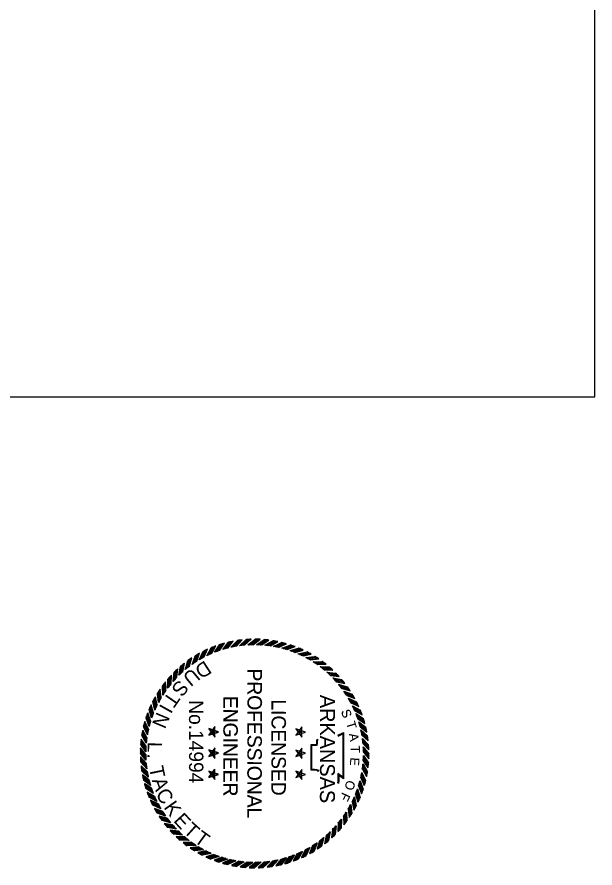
# Model space of a CAD drawing. Extents: x -206535075 to -206533174, y 123969740 to 123973355.
# Drawn here: x -206534124 to -206533511, y 123969740 to 123970644 of the extents above; entities that cross this region are included whole.
import ezdxf

# ---------------------------------------------------------------- set-up
doc = ezdxf.new("R2010")
doc.units = 0
doc.layers.add('54', color=7, linetype='Continuous')
doc.layers.add('Default', color=7, linetype='Continuous')

# ---------------------------------------------------------------- blocks, each defined once
blk = doc.blocks.new('STAR')
at = {"layer": 'Default'}
for p, q in [((0.0587, 0.0188), (-0.059, 0.0189)), ((-0.0589, 0.0188), (0.0363, -0.0505)), ((-0.0001, 0.0615), (-0.0366, -0.0504)), ((-0.0365, -0.0503), (0.0589, 0.0188)), ((-0.0085, 0), (0.009, 0)), ((0.0362, -0.0503), (0, 0.0617)), ((0, 0.0063), (0, -0.0085))]:
    blk.add_line(p, q, dxfattribs=at)
blk = doc.blocks.new('RP')
at = {"layer": 'Default'}
for p, q in [((-0.0781, 1.2656), (0.003, 1.33)), ((-0.058, 1.2667), (0.0216, 1.3299)), ((-0.0375, 1.2674), (0.0405, 1.3294)), ((-0.0176, 1.2679), (0.059, 1.3287))]:
    blk.add_line(p, q, dxfattribs=at)
for radius, start, end in [(1.33, 87.45624, 89.86992), (1.268, 90.79335, 93.53072)]:
    blk.add_arc((0, 0), radius, start, end, dxfattribs=at)

msp = doc.modelspace()

# ---------------------------------------------------------------- linework, layer by layer
at = {"layer": '54'}
msp.add_lwpolyline([(-206535027.79, 123970240.59), (-206533510.85, 123970240.59), (-206533510.85, 123973354.72), (-206535027.79, 123973354.72)], close=True, dxfattribs=at)
at = {"layer": 'Default'}
for points in [[(-206533804.55, 123969842.92), (-206533805.23, 123969843.76), (-206533806.25, 123969844.04), (-206533808.79, 123969844.33), (-206533812.18, 123969844.34), (-206533812.08, 123969871.71), (-206533807.51, 123969871.7), (-206533806.49, 123969871.69), (-206533806.15, 123969872.8), (-206533806.13, 123969876.7), (-206533805.08, 123969877.39)], [(-206533804.45, 123969842.94), (-206533805.13, 123969843.78), (-206533806.15, 123969844.06), (-206533808.69, 123969844.34), (-206533812.08, 123969844.34), (-206533812.08, 123969871.71), (-206533807.51, 123969871.71), (-206533806.49, 123969871.71), (-206533806.15, 123969872.82), (-206533806.15, 123969876.72), (-206533805.1, 123969877.41)], [(-206533803.95, 123969843.41), (-206533804.78, 123969844.44), (-206533806.1, 123969844.8), (-206533808.74, 123969845.1), (-206533811.4, 123969845.11), (-206533811.31, 123969870.93), (-206533807.51, 123969870.92), (-206533805.92, 123969870.91), (-206533805.37, 123969872.68), (-206533805.36, 123969876.27), (-206533804.65, 123969876.73)], [(-206533803.85, 123969843.44), (-206533804.69, 123969844.46), (-206533806.01, 123969844.82), (-206533808.65, 123969845.11), (-206533811.31, 123969845.11), (-206533811.31, 123969870.94), (-206533807.51, 123969870.94), (-206533805.92, 123969870.94), (-206533805.37, 123969872.71), (-206533805.37, 123969876.3), (-206533804.67, 123969876.76)], [(-206533783.55, 123969880.62), (-206533778.5, 123969882.93), (-206533778.63, 123969836.71), (-206533783.79, 123969840.85), (-206533783.74, 123969835.88), (-206533783.71, 123969833.14), (-206533784.02, 123969830.41)], [(-206533783.9, 123969881.42), (-206533777.76, 123969884.26), (-206533777.74, 123969835.22), (-206533782.88, 123969839.31), (-206533782.84, 123969835.98), (-206533782.8, 123969833.2), (-206533783.11, 123969830.42)], [(-206533783.58, 123969880.72), (-206533778.54, 123969883.04), (-206533778.51, 123969836.83), (-206533783.68, 123969840.94), (-206533783.62, 123969835.97), (-206533783.58, 123969833.24), (-206533783.88, 123969830.5)], [(-206533783.87, 123969881.33), (-206533777.72, 123969884.14), (-206533777.86, 123969835.1), (-206533782.99, 123969839.21), (-206533782.96, 123969835.88), (-206533782.94, 123969833.1), (-206533783.25, 123969830.32)]]:
    msp.add_lwpolyline(points, dxfattribs=at)

# ---------------------------------------------------------------- block references
for name, p, xscale, yscale, rotation in [('RP', (-206533872.18, 123969862.15), 91.17655343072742, 91.1765534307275, 22.30419999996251), ('RP', (-206533872.15, 123969861.95), 91.17655343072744, 91.17655343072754, 18.000000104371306), ('RP', (-206533872.18, 123969862.15), 91.17655343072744, 91.17655343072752, 17.804199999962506), ('RP', (-206533872.15, 123969861.95), 91.17655343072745, 91.17655343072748, 13.500000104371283), ('RP', (-206533872.18, 123969862.15), 91.17655343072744, 91.17655343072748, 13.304199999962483), ('RP', (-206533872.15, 123969861.95), 91.17655343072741, 91.17655343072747, 9.000000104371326), ('RP', (-206533872.18, 123969862.15), 91.17655343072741, 91.17655343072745, 8.804199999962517), ('RP', (-206533872.15, 123969861.95), 91.17655343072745, 91.17655343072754, 4.500000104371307), ('RP', (-206533872.18, 123969862.15), 91.17655343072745, 91.17655343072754, 4.3041999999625), ('RP', (-206533872.15, 123969861.95), 91.17655343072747, 91.17655343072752, 1.0437130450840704e-07), ('RP', (-206533872.18, 123969862.15), 91.17655343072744, 91.17655343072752, -0.1958000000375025), ('RP', (-206533872.15, 123969861.95), 91.17655343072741, 91.17655343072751, -4.499999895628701), ('RP', (-206533872.18, 123969862.15), 91.17655343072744, 91.1765534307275, -4.695800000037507), ('RP', (-206533872.15, 123969861.95), 91.17655343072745, 91.17655343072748, -8.999999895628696), ('RP', (-206533872.18, 123969862.15), 91.17655343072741, 91.17655343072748, -9.195800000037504), ('RP', (-206533872.15, 123969861.95), 91.17655343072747, 91.1765534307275, -13.499999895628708), ('RP', (-206533872.18, 123969862.15), 91.17655343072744, 91.1765534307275, -13.695800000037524), ('RP', (-206533872.15, 123969861.95), 91.17655343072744, 91.17655343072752, -17.999999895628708), ('RP', (-206533872.18, 123969862.15), 91.17655343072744, 91.1765534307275, -18.19580000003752), ('RP', (-206533872.15, 123969861.95), 91.17655343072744, 91.17655343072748, -22.499999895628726), ('RP', (-206533872.18, 123969862.15), 91.17655343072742, 91.17655343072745, -22.695800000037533), ('RP', (-206533872.15, 123969861.95), 91.17655343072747, 91.17655343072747, 31.500000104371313), ('RP', (-206533872.18, 123969862.15), 91.17655343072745, 91.17655343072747, 31.30419999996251), ('RP', (-206533872.15, 123969861.95), 91.17655343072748, 91.1765534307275, 27.0000001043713), ('RP', (-206533872.18, 123969862.15), 91.17655343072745, 91.17655343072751, 26.804199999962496), ('RP', (-206533872.15, 123969861.95), 91.17655343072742, 91.17655343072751, 22.500000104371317), ('RP', (-206533872.15, 123969861.95), 91.17655343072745, 91.17655343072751, -26.999999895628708), ('RP', (-206533872.18, 123969862.15), 91.17655343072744, 91.17655343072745, -27.195800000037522), ('RP', (-206533872.15, 123969861.95), 91.17655343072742, 91.17655343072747, -31.49999989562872), ('RP', (-206533872.18, 123969862.15), 91.17655343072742, 91.17655343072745, -31.695800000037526), ('RP', (-206533872.18, 123969862.15), 91.17655343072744, 91.17655343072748, 40.30419999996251), ('RP', (-206533872.15, 123969861.95), 91.17655343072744, 91.17655343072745, 36.00000010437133), ('RP', (-206533872.18, 123969862.15), 91.17655343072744, 91.17655343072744, 35.80419999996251), ('RP', (-206533872.15, 123969861.95), 91.17655343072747, 91.17655343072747, -35.999999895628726), ('RP', (-206533872.18, 123969862.15), 91.17655343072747, 91.17655343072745, -36.19580000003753), ('RP', (-206533872.15, 123969861.95), 91.17655343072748, 91.1765534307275, -40.49999989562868), ('RP', (-206533872.18, 123969862.15), 91.1765534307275, 91.17655343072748, -40.695800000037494), ('RP', (-206533872.15, 123969861.95), 91.17655343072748, 91.17655343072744, 45.000000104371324), ('RP', (-206533872.18, 123969862.15), 91.17655343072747, 91.17655343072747, 44.80419999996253), ('RP', (-206533872.15, 123969861.95), 91.17655343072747, 91.17655343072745, 40.50000010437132), ('RP', (-206533872.15, 123969861.95), 91.17655343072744, 91.17655343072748, -44.99999989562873), ('RP', (-206533872.18, 123969862.15), 91.17655343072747, 91.17655343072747, -45.195800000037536), ('RP', (-206533872.15, 123969861.95), 91.1765534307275, 91.17655343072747, 49.50000010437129), ('RP', (-206533872.18, 123969862.15), 91.17655343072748, 91.17655343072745, 49.30419999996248), ('RP', (-206533872.15, 123969861.95), 91.17655343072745, 91.17655343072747, -49.49999989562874), ('RP', (-206533872.18, 123969862.15), 91.17655343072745, 91.17655343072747, -49.69580000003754), ('RP', (-206533872.15, 123969861.95), 91.1765534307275, 91.17655343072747, 54.00000010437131), ('RP', (-206533872.18, 123969862.15), 91.17655343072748, 91.17655343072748, 53.80419999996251), ('RP', (-206533872.15, 123969861.95), 91.17655343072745, 91.17655343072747, -53.99999989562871), ('RP', (-206533872.18, 123969862.15), 91.17655343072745, 91.17655343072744, -54.19580000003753), ('RP', (-206533872.15, 123969861.95), 91.17655343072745, 91.17655343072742, -58.499999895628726), ('RP', (-206533872.18, 123969862.15), 91.17655343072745, 91.17655343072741, -58.69580000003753), ('RP', (-206533872.18, 123969862.15), 91.17655343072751, 91.17655343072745, 62.8041999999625), ('RP', (-206533872.15, 123969861.95), 91.17655343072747, 91.17655343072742, 58.50000010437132), ('RP', (-206533872.18, 123969862.15), 91.17655343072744, 91.17655343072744, 58.3041999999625), ('RP', (-206533872.15, 123969861.95), 91.1765534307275, 91.17655343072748, -62.999999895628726), ('RP', (-206533872.18, 123969862.15), 91.1765534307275, 91.17655343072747, -63.195800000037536), ('RP', (-206533872.15, 123969861.95), 91.17655343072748, 91.17655343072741, 67.50000010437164), ('RP', (-206533872.18, 123969862.15), 91.17655343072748, 91.17655343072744, 67.30419999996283), ('RP', (-206533872.15, 123969861.95), 91.17655343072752, 91.17655343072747, 63.00000010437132), ('RP', (-206533872.15, 123969861.95), 91.1765534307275, 91.17655343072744, -67.49999989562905), ('RP', (-206533872.18, 123969862.15), 91.17655343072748, 91.17655343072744, -67.69580000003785), ('RP', (-206533872.15, 123969861.95), 91.17655343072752, 91.17655343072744, 72.0000001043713), ('RP', (-206533872.18, 123969862.15), 91.17655343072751, 91.17655343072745, 71.80419999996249), ('RP', (-206533872.15, 123969861.95), 91.1765534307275, 91.17655343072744, -71.9999998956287), ('RP', (-206533872.18, 123969862.15), 91.17655343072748, 91.17655343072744, -72.19580000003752), ('RP', (-206533872.15, 123969861.95), 91.1765534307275, 91.17655343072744, 76.5000001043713), ('RP', (-206533872.18, 123969862.15), 91.1765534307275, 91.17655343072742, 76.30419999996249), ('RP', (-206533872.15, 123969861.95), 91.17655343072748, 91.17655343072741, -76.4999998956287), ('RP', (-206533872.18, 123969862.15), 91.1765534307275, 91.17655343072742, -76.69580000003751), ('RP', (-206533872.18, 123969862.15), 91.1765534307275, 91.17655343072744, 80.80419999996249), ('RP', (-206533872.15, 123969861.95), 91.17655343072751, 91.17655343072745, 81.0000001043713), ('STAR', (-206533916.21, 123969884.84), 91.1765534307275, 91.1765534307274, -89.9999998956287), ('STAR', (-206533916.16, 123969885.19), 91.1765534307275, 91.17655343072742, -90.1958000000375), ('STAR', (-206533823.73, 123969884.84), 91.1765534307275, 91.1765534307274, -89.9999998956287), ('STAR', (-206533823.69, 123969884.88), 91.1765534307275, 91.17655343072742, -90.1958000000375), ('RP', (-206533872.15, 123969861.95), 91.17655343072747, 91.1765534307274, -80.9999998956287), ('RP', (-206533872.18, 123969862.15), 91.17655343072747, 91.1765534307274, -81.19580000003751), ('RP', (-206533872.18, 123969862.15), 91.17655343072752, 91.17655343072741, 85.30419999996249), ('RP', (-206533872.15, 123969861.95), 91.1765534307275, 91.17655343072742, 85.5000001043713), ('RP', (-206533872.15, 123969861.95), 91.17655343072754, 91.17655343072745, -85.4999998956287), ('RP', (-206533872.18, 123969862.15), 91.17655343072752, 91.17655343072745, -85.69580000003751), ('RP', (-206533872.18, 123969862.15), 91.17655343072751, 91.17655343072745, 89.80419999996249), ('STAR', (-206533916.24, 123969862.64), 91.1765534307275, 91.17655343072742, -90.1958000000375), ('STAR', (-206533916.21, 123969862.28), 91.1765534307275, 91.1765534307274, -89.9999998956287), ('STAR', (-206533823.76, 123969862.32), 91.1765534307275, 91.17655343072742, -90.1958000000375), ('STAR', (-206533823.73, 123969862.28), 91.1765534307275, 91.1765534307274, -89.9999998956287), ('RP', (-206533872.18, 123969862.15), 91.1765534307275, 91.17655343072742, -90.1958000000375), ('RP', (-206533872.15, 123969861.95), 91.1765534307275, 91.1765534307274, -89.9999998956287), ('RP', (-206533872.18, 123969862.15), 91.1765534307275, 91.17655343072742, 94.30419999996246), ('RP', (-206533872.15, 123969861.95), 91.17655343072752, 91.17655343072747, 90.0000001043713), ('RP', (-206533872.18, 123969862.15), 91.1765534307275, 91.17655343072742, -94.69580000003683), ('RP', (-206533872.15, 123969861.95), 91.1765534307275, 91.17655343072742, -94.49999989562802), ('RP', (-206533872.15, 123969861.95), 91.17655343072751, 91.17655343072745, 94.50000010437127), ('RP', (-206533872.18, 123969862.15), 91.17655343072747, 91.1765534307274, 98.80419999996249), ('RP', (-206533872.18, 123969862.15), 91.1765534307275, 91.1765534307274, -99.19580000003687), ('RP', (-206533872.15, 123969861.95), 91.17655343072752, 91.17655343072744, -98.99999989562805), ('RP', (-206533872.15, 123969861.95), 91.17655343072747, 91.1765534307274, 99.00000010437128), ('RP', (-206533872.18, 123969862.15), 91.17655343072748, 91.17655343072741, 103.30419999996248), ('STAR', (-206533916.32, 123969840.09), 91.1765534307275, 91.17655343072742, -90.1958000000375), ('STAR', (-206533916.21, 123969839.73), 91.1765534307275, 91.1765534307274, -89.9999998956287), ('STAR', (-206533823.84, 123969839.77), 91.1765534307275, 91.17655343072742, -90.1958000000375), ('STAR', (-206533823.73, 123969839.73), 91.1765534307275, 91.1765534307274, -89.9999998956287), ('RP', (-206533872.18, 123969862.15), 91.17655343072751, 91.17655343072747, -103.69580000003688), ('RP', (-206533872.15, 123969861.95), 91.17655343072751, 91.17655343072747, -103.49999989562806), ('RP', (-206533872.15, 123969861.95), 91.17655343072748, 91.1765534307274, 103.50000010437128), ('RP', (-206533872.18, 123969862.15), 91.1765534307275, 91.17655343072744, 107.80419999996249), ('RP', (-206533872.18, 123969862.15), 91.17655343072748, 91.17655343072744, -108.19580000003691), ('RP', (-206533872.15, 123969861.95), 91.17655343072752, 91.17655343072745, -107.9999998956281), ('RP', (-206533872.15, 123969861.95), 91.1765534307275, 91.17655343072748, 108.0000001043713), ('RP', (-206533872.18, 123969862.15), 91.17655343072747, 91.17655343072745, 112.30419999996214), ('RP', (-206533872.15, 123969861.95), 91.1765534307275, 91.17655343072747, 112.50000010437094), ('RP', (-206533872.18, 123969862.15), 91.1765534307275, 91.17655343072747, -112.69580000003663), ('RP', (-206533872.15, 123969861.95), 91.17655343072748, 91.17655343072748, -112.49999989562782), ('RP', (-206533872.18, 123969862.15), 91.17655343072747, 91.1765534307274, 116.80419999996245), ('RP', (-206533872.15, 123969861.95), 91.17655343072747, 91.17655343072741, 117.00000010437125), ('RP', (-206533872.18, 123969862.15), 91.17655343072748, 91.17655343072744, -117.19580000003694), ('RP', (-206533872.15, 123969861.95), 91.17655343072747, 91.17655343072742, -116.99999989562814), ('RP', (-206533872.18, 123969862.15), 91.17655343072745, 91.17655343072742, 121.30419999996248), ('RP', (-206533872.15, 123969861.95), 91.17655343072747, 91.17655343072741, 121.50000010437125), ('RP', (-206533872.18, 123969862.15), 91.17655343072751, 91.17655343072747, -121.69580000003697), ('RP', (-206533872.15, 123969861.95), 91.17655343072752, 91.17655343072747, -121.49999989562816), ('RP', (-206533872.18, 123969862.15), 91.17655343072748, 91.17655343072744, 125.80419999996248), ('RP', (-206533872.15, 123969861.95), 91.17655343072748, 91.17655343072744, 126.00000010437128), ('RP', (-206533872.18, 123969862.15), 91.1765534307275, 91.17655343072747, -126.195800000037), ('RP', (-206533872.15, 123969861.95), 91.17655343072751, 91.17655343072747, -125.99999989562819), ('RP', (-206533872.18, 123969862.15), 91.17655343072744, 91.17655343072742, 130.3041999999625), ('RP', (-206533872.15, 123969861.95), 91.17655343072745, 91.17655343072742, 130.5000001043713), ('RP', (-206533872.18, 123969862.15), 91.17655343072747, 91.17655343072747, -130.69580000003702), ('RP', (-206533872.15, 123969861.95), 91.17655343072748, 91.17655343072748, -130.4999998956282), ('RP', (-206533872.18, 123969862.15), 91.17655343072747, 91.17655343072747, 134.80419999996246), ('RP', (-206533872.15, 123969861.95), 91.17655343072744, 91.17655343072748, 135.00000010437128), ('RP', (-206533872.18, 123969862.15), 91.17655343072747, 91.17655343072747, 139.30419999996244), ('RP', (-206533872.15, 123969861.95), 91.17655343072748, 91.17655343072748, 139.50000010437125), ('RP', (-206533872.18, 123969862.15), 91.17655343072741, 91.17655343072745, -139.69580000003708), ('RP', (-206533872.15, 123969861.95), 91.17655343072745, 91.17655343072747, -139.49999989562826), ('RP', (-206533872.18, 123969862.15), 91.1765534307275, 91.17655343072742, -135.19580000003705), ('RP', (-206533872.15, 123969861.95), 91.17655343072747, 91.17655343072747, -134.9999998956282), ('RP', (-206533872.18, 123969862.15), 91.17655343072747, 91.1765534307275, 143.80419999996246), ('RP', (-206533872.15, 123969861.95), 91.17655343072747, 91.1765534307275, 144.00000010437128), ('RP', (-206533872.18, 123969862.15), 91.17655343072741, 91.17655343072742, -144.19580000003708), ('RP', (-206533872.15, 123969861.95), 91.17655343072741, 91.17655343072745, -143.9999998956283), ('RP', (-206533872.18, 123969862.15), 91.17655343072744, 91.1765534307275, 148.3041999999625), ('RP', (-206533872.15, 123969861.95), 91.17655343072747, 91.1765534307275, 148.50000010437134), ('RP', (-206533872.18, 123969862.15), 91.17655343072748, 91.17655343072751, 152.80419999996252), ('RP', (-206533872.15, 123969861.95), 91.17655343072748, 91.17655343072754, 153.00000010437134), ('RP', (-206533872.18, 123969862.15), 91.17655343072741, 91.17655343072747, -153.19580000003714), ('RP', (-206533872.15, 123969861.95), 91.17655343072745, 91.17655343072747, -152.99999989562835), ('RP', (-206533872.18, 123969862.15), 91.17655343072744, 91.17655343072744, -148.6958000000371), ('RP', (-206533872.15, 123969861.95), 91.17655343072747, 91.17655343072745, -148.49999989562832), ('RP', (-206533872.18, 123969862.15), 91.17655343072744, 91.17655343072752, 157.30419999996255), ('RP', (-206533872.15, 123969861.95), 91.17655343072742, 91.1765534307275, 157.50000010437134), ('RP', (-206533872.18, 123969862.15), 91.17655343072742, 91.17655343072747, 161.80419999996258), ('RP', (-206533872.15, 123969861.95), 91.17655343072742, 91.17655343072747, 162.00000010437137), ('RP', (-206533872.18, 123969862.15), 91.17655343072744, 91.17655343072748, 166.3041999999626), ('RP', (-206533872.15, 123969861.95), 91.17655343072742, 91.17655343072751, 166.5000001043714), ('RP', (-206533872.18, 123969862.15), 91.17655343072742, 91.17655343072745, -166.69580000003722), ('RP', (-206533872.15, 123969861.95), 91.17655343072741, 91.17655343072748, -166.4999998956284), ('RP', (-206533872.18, 123969862.15), 91.17655343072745, 91.17655343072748, -162.19580000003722), ('RP', (-206533872.15, 123969861.95), 91.17655343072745, 91.17655343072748, -161.9999998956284), ('RP', (-206533872.18, 123969862.15), 91.17655343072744, 91.17655343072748, -157.69580000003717), ('RP', (-206533872.15, 123969861.95), 91.17655343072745, 91.17655343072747, -157.49999989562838), ('RP', (-206533872.18, 123969862.15), 91.17655343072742, 91.1765534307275, 170.80419999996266), ('RP', (-206533872.15, 123969861.95), 91.17655343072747, 91.1765534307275, 171.00000010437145), ('RP', (-206533872.18, 123969862.15), 91.17655343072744, 91.1765534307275, 175.30419999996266), ('RP', (-206533872.15, 123969861.95), 91.17655343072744, 91.17655343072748, 175.50000010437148), ('RP', (-206533872.18, 123969862.15), 91.17655343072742, 91.17655343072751, 179.8041999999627), ('RP', (-206533872.15, 123969861.95), 91.17655343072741, 91.17655343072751, -179.99999989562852), ('RP', (-206533872.18, 123969862.15), 91.17655343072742, 91.1765534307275, -175.6958000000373), ('RP', (-206533872.15, 123969861.95), 91.17655343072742, 91.1765534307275, -175.49999989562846), ('RP', (-206533872.18, 123969862.15), 91.17655343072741, 91.17655343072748, -171.19580000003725), ('RP', (-206533872.15, 123969861.95), 91.17655343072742, 91.1765534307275, -170.99999989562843)]:
    msp.add_blockref(name, p, dxfattribs=dict(at, xscale=xscale, yscale=yscale, rotation=rotation))

# ---------------------------------------------------------------- texts
for s, height, rotation, p in [('D', 15.28, 212.90454, (-206533924.7, 123969961.3)), ('U', 15.28, 219.81311, (-206533938.32, 123969953.55)), ('PROFESSIONAL', 15.2848, 269.8042, (-206533879.51, 123969952.43)), ('PROFESSIONAL', 15.2848, 270, (-206533879.79, 123969952.2)), ('S', 15.28, 230.36795, (-206533952.61, 123969941.24)), ('T', 15.28, 235.10102, (-206533963.04, 123969928.9)), ('ARKANSAS', 15.788, 269.8042, (-206533802.51, 123969924.31)), ('ARKANSAS', 15.788, 270, (-206533802.69, 123969924.35)), ('I', 15.28, 240.86866, (-206533971.58, 123969915.76)), ('No.14994', 15.225, 270, (-206533941.79, 123969918.62)), ('ENGINEER', 15.285, 270, (-206533905.35, 123969923.08)), ('ENGINEER', 15.285, 269.8042, (-206533905.17, 123969923.4)), ('LICENSED', 15.285, 269.8042, (-206533854.06, 123969919.59)), ('LICENSED', 15.285, 270, (-206533854.23, 123969919.45)), ('N', 15.28, 247.25385, (-206533975.72, 123969906.9)), ('S', 9.67, 289.77256, (-206533780.69, 123969906.97)), ('S', 9.67, 289.57676, (-206533780.56, 123969906.86)), ('T', 9.67, 286.90148, (-206533775.16, 123969894.66)), ('T', 9.67, 286.70568, (-206533775.08, 123969894.54)), ('A', 9.67, 278.67877, (-206533772.1, 123969882.92)), ('A', 9.67, 278.48297, (-206533772.06, 123969882.78)), ('L', 15.28, 268.47397, (-206533985.57, 123969874.56)), ('T', 9.67, 271.28307, (-206533770.18, 123969870.28)), ('T', 9.67, 271.47887, (-206533770.17, 123969870.43)), ('.', 15.28, 274.14887, (-206533986.3, 123969862.07)), ('T', 15.28, 281.73028, (-206533984.38, 123969847.19)), ('E', 9.67, 266.47623, (-206533770.51, 123969857.9)), ('E', 9.67, 266.67203, (-206533770.46, 123969858.05)), ('A', 15.28, 289.38171, (-206533981.41, 123969833.54)), ('O', 9.67, 251.026, (-206533773.91, 123969834.43)), ('O', 9.67, 251.2218, (-206533773.78, 123969834.56)), ('C', 15.28, 303.65767, (-206533977.89, 123969818.86)), ('F', 9.67, 245.16702, (-206533779.05, 123969821.41)), ('F', 9.67, 245.36282, (-206533778.88, 123969821.52)), ('K', 15.28, 305.12182, (-206533969.19, 123969804.82)), ('E', 15.28, 312.43923, (-206533958.98, 123969790.29)), ('T', 15.28, 318.07465, (-206533948.68, 123969778.83)), ('T', 15.28, 324.3036, (-206533937.35, 123969768.87))]:
    msp.add_text(s, height=height, rotation=rotation, dxfattribs=at).set_placement(p)

doc.saveas('drawing.dxf')
